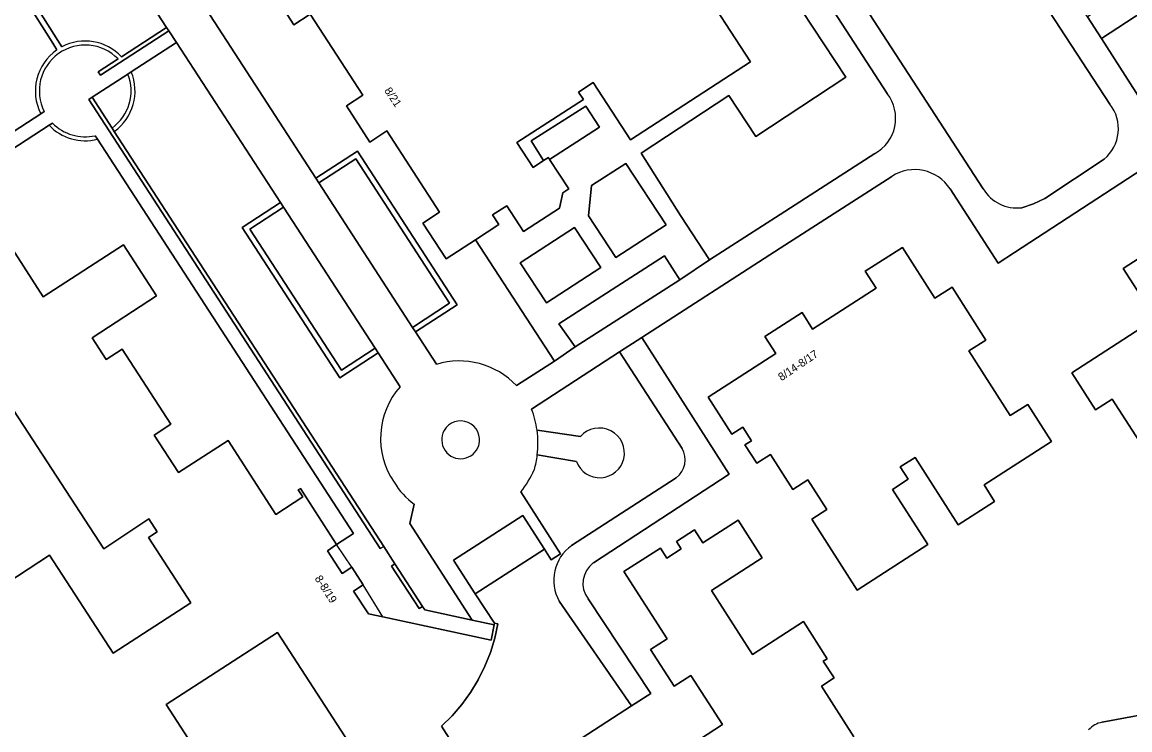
# Model space of a CAD drawing. Extents: x 159451 to 160664, y 388402 to 389723.
# Drawn here: x 159905.3 to 160043.7, y 389113.3 to 389201.7 of the extents above; entities that cross this region are included whole.
import ezdxf

# ---------------------------------------------------------------- set-up
doc = ezdxf.new("R2010")
doc.units = 0
for name, color, linetype in [('IMGEO_Erf', 7, 'Continuous'), ('IMGEO_Grasland_overig', 7, 'Continuous'), ('IMGEO_Groenvoorziening', 7, 'Continuous'), ('IMGEO_Haag', 7, 'Continuous'), ('IMGEO_Loofbos', 7, 'Continuous'), ('IMGEO_Pand', 7, 'Continuous'), ('IMGEO_Pand_nummerreeks', 7, 'Continuous'), ('IMGEO_Pand_overbouw', 7, 'Continuous'), ('IMGEO_Parkeervlak_gesloten', 7, 'Continuous'), ('IMGEO_Parkeervlak_open', 7, 'Continuous'), ('IMGEO_Rijbaan_lokaal_open', 7, 'Continuous'), ('IMGEO_Voetpad_gesloten', 7, 'Continuous'), ('IMGEO_Voetpad_open', 7, 'Continuous')]:
    doc.layers.add(name, color=color, linetype=linetype)

msp = doc.modelspace()

# ---------------------------------------------------------------- linework, layer by layer
at = {"layer": 'IMGEO_Erf'}
for points in [[(160071.89, 389220.37), (160040.16, 389199.62), (160049.04, 389185.76), (160029.31, 389172.93), (160027.27, 389171.6), (160021.26, 389180.85)], [(159908.65, 389188.8), (159892.09, 389178.04)], [(159904.05, 389173.41), (159907.94, 389167.36), (159917.95, 389173.87), (159922.1, 389167.52), (159914.03, 389162.25), (159915.78, 389159.56), (159917.79, 389160.86), (159923.89, 389151.47), (159921.79, 389150.11), (159924.82, 389145.44), (159931.02, 389149.46), (159937, 389140.22), (159940.37, 389142.4), (159939.8, 389143.29), (159940.07, 389143.45), (159944.59, 389136.47), (159946.68, 389137.83), (159914.71, 389187.05)], [(160013.96, 389182.42), (160000, 389173.44), (159982.74, 389162.32), (159993.64, 389145.22), (159976.67, 389134.17)], [(160045.85, 389166.32), (160042.88, 389170.93), (160053.34, 389177.67)], [(160046.95, 389146.17), (160041.51, 389154.6), (160039.44, 389153.27), (160036.46, 389157.9), (160049.34, 389166.2)], [(159986.93, 389110.15), (159992.8, 389113.99), (159988.87, 389120.11), (159986.77, 389118.76), (159983.82, 389123.35), (159985.9, 389124.68), (159980.5, 389133.07), (159985.06, 389136.01), (159985.86, 389134.76), (159987.65, 389135.91), (159987.08, 389136.81), (159989.33, 389138.27), (159990.37, 389136.65), (159994.76, 389139.48), (159997.77, 389134.8), (159991.42, 389130.72), (159996.56, 389122.73), (160002.93, 389126.83), (160005.91, 389122.2), (160005.41, 389121.88), (160006.76, 389119.8), (160005.18, 389118.78), (160009.24, 389112.46)], [(159976.01, 389129.66), (159983.84, 389117.87), (159981.42, 389116.3), (159963.52, 389104.72)], [(160040.24, 389114.26), (160063.58, 389118.6)]]:
    msp.add_lwpolyline(points, dxfattribs=at)
for points in [[(159999.48, 389160.31), (159998.11, 389162.44), (160002.75, 389165.41), (160004.06, 389163.36), (160012, 389168.46), (160010.64, 389170.57), (160015.3, 389173.55), (160019.36, 389167.23), (160021.49, 389168.59), (160025.73, 389161.98), (160023.6, 389160.62), (160028.77, 389152.55), (160030.95, 389153.95), (160033.92, 389149.32), (160025.49, 389143.91), (160026.82, 389141.83), (160022.27, 389138.9), (160016.87, 389147.32), (160015.03, 389146.14), (160016.02, 389144.6), (160014.05, 389143.34), (160018.47, 389136.44), (160009.63, 389130.77), (160003.97, 389139.6), (160005.86, 389140.82), (160003.48, 389144.54), (160001.6, 389143.33), (159998.8, 389147.69), (159997.1, 389146.6), (159995.62, 389148.9), (159996.44, 389149.42), (159995.36, 389151.1), (159993.98, 389150.22), (159991, 389154.87)], [(159926.37, 389129.16), (159921.08, 389137.31), (159922.18, 389138.02), (159921.11, 389139.65), (159915.48, 389135.92), (159900.68, 389158.6), (159902.96, 389160.02), (159901.31, 389162.64), (159887.76, 389154.14), (159891.55, 389148.29), (159893.57, 389149.61), (159900.41, 389139.07), (159896.4, 389136.48), (159900.67, 389129.9), (159908.73, 389135.13), (159916.68, 389122.87)], [(159951.56, 389103.31), (159937.2, 389125.47), (159923.3, 389116.46), (159937.66, 389094.3)]]:
    msp.add_lwpolyline(points, close=True, dxfattribs=at)
for centre, radius, start, end in [((159913.17, 389193.09), 6.23, 223.4934, 284.2887), ((160016.82, 389177.97), 5.29, 32.9971, 122.7747), ((159978.59, 389131.58), 3.22, 126.6873, 216.5787), ((160040.79, 389111.31), 3, 100.5123, 137.95)]:
    msp.add_arc(centre, radius, start, end, dxfattribs=at)
at = {"layer": 'IMGEO_Grasland_overig'}
for points in [[(159980.71, 389184.04), (159976.46, 389181.27), (159976.05, 389177.48), (159979.48, 389172.27), (159985.77, 389176.35)], [(159974.31, 389176.02), (159967.54, 389171.61), (159970.82, 389166.63), (159977.59, 389171.04)], [(159987.48, 389169.5), (159985.55, 389172.48), (159972.36, 389164.01), (159974.39, 389161.13)], [(159951.88, 389134.03), (159951.46, 389133.76), (159954.91, 389128.45), (159955.33, 389128.72)]]:
    msp.add_lwpolyline(points, close=True, dxfattribs=at)
at = {"layer": 'IMGEO_Groenvoorziening'}
for points in [[(159917.7, 389197.36), (159923.34, 389201.02), (159906.77, 389226.48)], [(159890.55, 389218.64), (159894.92, 389221.41), (159895.56, 389221.81), (159910.27, 389198.6)], [(159895.56, 389221.81), (159894.92, 389221.41), (159909.11, 389199.03), (159909.62, 389198.21)], [(159910.27, 389198.6), (159895.56, 389221.81)], [(159945.81, 389191.21), (159947.88, 389192.55), (159941.29, 389202.68), (159939.26, 389201.36), (159936.36, 389205.82), (159942.76, 389209.97), (159942.59, 389210.24), (159932.13, 389203.53), (159929.12, 389208.23), (159926.29, 389206.42), (159942, 389182.2), (159947.2, 389185.57), (159959.65, 389166.36), (159954.45, 389162.99), (159957.06, 389158.96)], [(160013.39, 389192.75), (160004.14, 389207.04), (160001.35, 389205.26), (160008.23, 389194.81), (159996.97, 389187.41), (159993.6, 389192.53), (159982.65, 389185.33), (159987.56, 389177.52), (159991.19, 389171.98), (160000, 389177.64), (160011.84, 389185.26)], [(159917.28, 389197.08), (159914.79, 389195.47), (159915.07, 389195.05), (159923.61, 389200.6), (159923.34, 389201.02), (159917.7, 389197.36)], [(159924.57, 389199.14), (159918.93, 389195.47)], [(159952.53, 389156.15), (159949.79, 389160.37), (159945.01, 389157.26), (159932.8, 389176.04), (159937.57, 389179.15), (159924.57, 389199.14)], [(159918.5, 389195.2), (159914.04, 389192.3), (159916.54, 389188.45)], [(159918.93, 389195.47), (159918.5, 389195.2)], [(159907.64, 389190.23), (159908.06, 389190.5)], [(159967.08, 389156.3), (159971.81, 389159.35), (159961.96, 389174.51), (159958.27, 389172.11), (159955.36, 389176.58), (159957.45, 389177.93), (159950.85, 389188.09), (159948.73, 389186.71), (159945.81, 389191.21)], [(159909.08, 389189.08), (159908.65, 389188.8)], [(159914.71, 389187.05), (159914.42, 389187.49)], [(159916.54, 389188.45), (159916.81, 389188.03)], [(159916.81, 389188.03), (159950.47, 389136.21), (159951.88, 389134.03), (159955.33, 389128.72), (159955.62, 389128.28), (159961.53, 389127.02), (159953.74, 389139.06), (159954.29, 389141.51)], [(159987.77, 389148.46), (159979.95, 389160.51), (159968.95, 389153.36)], [(159969.63, 389150.72), (159975.05, 389149.93)], [(159974.57, 389146.81), (159969.67, 389147.64)], [(159973.96, 389136.33), (159987.03, 389144.79)], [(159967.6, 389143.02), (159972.56, 389135.28), (159971.42, 389134.54), (159970.58, 389135.89), (159961.91, 389130.28), (159964.33, 389126.63), (159964.73, 389126.55), (159964.35, 389124.76), (159963.81, 389122.98), (159963.12, 389121.25), (159962.29, 389119.57), (159961.32, 389117.97), (159960.22, 389116.47), (159959.01, 389115.07), (159957.7, 389113.79), (159961.75, 389107.46), (159963.52, 389104.72), (159981.42, 389116.3), (159972.41, 389129.37)]]:
    msp.add_lwpolyline(points, dxfattribs=at)
for points in [[(159916.81, 389188.03), (159916.54, 389188.45), (159914.04, 389192.3), (159913.62, 389192.03), (159950.05, 389135.94), (159950.47, 389136.21)], [(159970.46, 389184.38), (159971.06, 389184.77), (159971.21, 389184.53), (159977.42, 389188.57), (159975.75, 389191.2), (159968.9, 389186.86)], [(159954.45, 389162.99), (159959.65, 389166.36), (159947.2, 389185.57), (159942, 389182.2), (159942.38, 389181.61), (159946.99, 389184.6), (159958.69, 389166.57), (159954.07, 389163.57)], [(159949.41, 389160.96), (159945.22, 389158.23), (159933.76, 389175.84), (159937.96, 389178.56), (159937.57, 389179.15), (159932.8, 389176.04), (159945.01, 389157.26), (159949.79, 389160.37)]]:
    msp.add_lwpolyline(points, close=True, dxfattribs=at)
for centre, radius, start, end in [((159913.17, 389193.09), 5.73, 44.2159, 206.8512), ((159913.17, 389193.09), 6.23, 43.3041, 117.7763), ((159913.17, 389193.09), 6.23, 43.3041, 117.7763), ((159913.17, 389193.09), 6.23, 124.6712, 207.3407), ((159913.17, 389193.09), 5.73, 306.0016, 21.5831), ((159913.17, 389193.09), 5.73, 306.0016, 21.5831), ((159913.17, 389193.09), 6.23, 305.7753, 22.5008), ((159913.17, 389193.09), 6.23, 305.7753, 22.5008), ((160009.42, 389189.66), 5.03, 298.8712, 37.8537), ((159913.17, 389193.09), 6.23, 223.4934, 284.2887), ((159913.17, 389193.09), 5.73, 224.4279, 282.5875), ((159959.91, 389149.48), 9.89, 43.552, 106.7454), ((159959.76, 389149.71), 9.68, 138.2961, 214.3823), ((159957.64, 389149.04), 12.11, 7.9949, 20.9234), ((159977.42, 389147.86), 3.14, 347.055, 138.8731), ((159985.31, 389147.04), 2.84, 307.436, 29.9141), ((159957.59, 389149.05), 12.16, 344.4296, 353.3315), ((159977.47, 389147.88), 3.09, 200.2256, 346.5119), ((159958.03, 389150.8), 12.33, 320.8729, 336.0275), ((159959.31, 389148.67), 8.74, 210.441, 234.976), ((159977.01, 389131.99), 5.3, 125.1, 209.6489)]:
    msp.add_arc(centre, radius, start, end, dxfattribs=at)
at = {"layer": 'IMGEO_Haag'}
for points in [[(159895.56, 389221.81), (159894.92, 389221.41), (159909.11, 389199.03), (159909.62, 389198.21)], [(159910.27, 389198.6), (159895.56, 389221.81)], [(159917.28, 389197.08), (159914.79, 389195.47), (159915.07, 389195.05), (159923.61, 389200.6), (159923.34, 389201.02), (159917.7, 389197.36)], [(159918.5, 389195.2), (159914.04, 389192.3), (159916.54, 389188.45)], [(159918.93, 389195.47), (159918.5, 389195.2)], [(159907.64, 389190.23), (159908.06, 389190.5)], [(159909.08, 389189.08), (159908.65, 389188.8)], [(159914.71, 389187.05), (159914.42, 389187.49)], [(159916.54, 389188.45), (159916.81, 389188.03)]]:
    msp.add_lwpolyline(points, dxfattribs=at)
for points in [[(159916.81, 389188.03), (159916.54, 389188.45), (159914.04, 389192.3), (159913.62, 389192.03), (159950.05, 389135.94), (159950.47, 389136.21)], [(159954.45, 389162.99), (159959.65, 389166.36), (159947.2, 389185.57), (159942, 389182.2), (159942.38, 389181.61), (159946.99, 389184.6), (159958.69, 389166.57), (159954.07, 389163.57)], [(159949.41, 389160.96), (159945.22, 389158.23), (159933.76, 389175.84), (159937.96, 389178.56), (159937.57, 389179.15), (159932.8, 389176.04), (159945.01, 389157.26), (159949.79, 389160.37)], [(159951.88, 389134.03), (159951.46, 389133.76), (159954.91, 389128.45), (159955.33, 389128.72)]]:
    msp.add_lwpolyline(points, close=True, dxfattribs=at)
for radius, start, end in [(5.73, 44.2159, 206.8512), (6.23, 43.3041, 117.7763), (6.23, 124.6712, 207.3407), (5.73, 306.0016, 21.5831), (5.73, 306.0016, 21.5831), (6.23, 305.7753, 22.5008), (6.23, 223.4934, 284.2887), (5.73, 224.4279, 282.5875)]:
    msp.add_arc((159913.17, 389193.09), radius, start, end, dxfattribs=at)
at = {"layer": 'IMGEO_Loofbos'}
msp.add_lwpolyline([(160063.58, 389118.6), (160040.24, 389114.26)], dxfattribs=at)
msp.add_arc((160040.79, 389111.31), 3, 100.5123, 137.95, dxfattribs=at)
at = {"layer": 'IMGEO_Pand'}
for points in [[(159936.36, 389205.82), (159939.26, 389201.36), (159941.29, 389202.68), (159947.88, 389192.55), (159945.81, 389191.21), (159948.73, 389186.71), (159950.85, 389188.09), (159957.45, 389177.93), (159955.36, 389176.58), (159958.27, 389172.11), (159961.96, 389174.51), (159964.86, 389176.4), (159964.08, 389177.6), (159965.87, 389178.76), (159967.96, 389175.54), (159972.46, 389178.46), (159972.87, 389180.38), (159973.6, 389180.85), (159971.21, 389184.53), (159971.06, 389184.77), (159970.46, 389184.38), (159969.15, 389183.53), (159967.13, 389186.64), (159975.43, 389192.02), (159974.82, 389192.95), (159976.66, 389194.15), (159981.31, 389186.99), (159996.29, 389196.72), (159989.51, 389207.16)], [(160053.34, 389177.67), (160042.88, 389170.93), (160045.85, 389166.32)], [(159961.75, 389107.46), (159957.7, 389113.79), (159959.01, 389115.07), (159960.22, 389116.47), (159961.32, 389117.97), (159962.29, 389119.57), (159963.12, 389121.25), (159963.81, 389122.98), (159964.35, 389124.76), (159964.73, 389126.55), (159964.33, 389126.63), (159964.29, 389126.42), (159963.89, 389124.52), (159950.37, 389127.41), (159948.58, 389127.79), (159946.7, 389130.65), (159947.9, 389131.43), (159946.48, 389133.63), (159945.27, 389132.84), (159943.44, 389135.68), (159944.59, 389136.47), (159940.07, 389143.45), (159939.8, 389143.29), (159940.37, 389142.4), (159937, 389140.22), (159931.02, 389149.46), (159924.82, 389145.44), (159921.79, 389150.11), (159923.89, 389151.47), (159917.79, 389160.86), (159915.78, 389159.56), (159914.03, 389162.25), (159922.1, 389167.52), (159917.95, 389173.87), (159907.94, 389167.36), (159904.05, 389173.41)], [(160049.34, 389166.2), (160036.46, 389157.9), (160039.44, 389153.27), (160041.51, 389154.6), (160046.95, 389146.17)], [(160009.24, 389112.46), (160005.18, 389118.78), (160006.76, 389119.8), (160005.41, 389121.88), (160005.91, 389122.2), (160002.93, 389126.83), (159996.56, 389122.73), (159991.42, 389130.72), (159997.77, 389134.8), (159994.76, 389139.48), (159990.37, 389136.65), (159989.33, 389138.27), (159987.08, 389136.81), (159987.65, 389135.91), (159985.86, 389134.76), (159985.06, 389136.01), (159980.5, 389133.07), (159985.9, 389124.68), (159983.82, 389123.35), (159986.77, 389118.76), (159988.87, 389120.11), (159992.8, 389113.99), (159986.93, 389110.15)]]:
    msp.add_lwpolyline(points, dxfattribs=at)
for points in [[(160009.63, 389130.77), (160018.47, 389136.44), (160014.05, 389143.34), (160016.02, 389144.6), (160015.03, 389146.14), (160016.87, 389147.32), (160022.27, 389138.9), (160026.82, 389141.83), (160025.49, 389143.91), (160033.92, 389149.32), (160030.95, 389153.95), (160028.77, 389152.55), (160023.6, 389160.62), (160025.73, 389161.98), (160021.49, 389168.59), (160019.36, 389167.23), (160015.3, 389173.55), (160010.64, 389170.57), (160012, 389168.46), (160004.06, 389163.36), (160002.75, 389165.41), (159998.11, 389162.44), (159999.48, 389160.31), (159991, 389154.87), (159993.98, 389150.22), (159995.36, 389151.1), (159996.44, 389149.42), (159995.62, 389148.9), (159997.1, 389146.6), (159998.8, 389147.69), (160001.6, 389143.33), (160003.48, 389144.54), (160005.86, 389140.82), (160003.97, 389139.6)], [(159916.68, 389122.87), (159908.73, 389135.13), (159900.67, 389129.9), (159896.4, 389136.48), (159900.41, 389139.07), (159893.57, 389149.61), (159891.55, 389148.29), (159887.76, 389154.14), (159901.31, 389162.64), (159902.96, 389160.02), (159900.68, 389158.6), (159915.48, 389135.92), (159921.11, 389139.65), (159922.18, 389138.02), (159921.08, 389137.31), (159926.37, 389129.16)], [(159937.66, 389094.3), (159923.3, 389116.46), (159937.2, 389125.47), (159951.56, 389103.31)]]:
    msp.add_lwpolyline(points, close=True, dxfattribs=at)
at = {"layer": 'IMGEO_Pand_overbouw'}
for points in [[(159946.48, 389133.63), (159944.59, 389136.47), (159943.44, 389135.68), (159945.27, 389132.84)], [(159950.37, 389127.41), (159947.9, 389131.43), (159946.7, 389130.65), (159948.58, 389127.79)]]:
    msp.add_lwpolyline(points, close=True, dxfattribs=at)
at = {"layer": 'IMGEO_Parkeervlak_gesloten'}
for points in [[(159891.49, 389221.76), (159884.5, 389217.18), (159885.42, 389215.73), (159881.22, 389213.01), (159898.21, 389186.19), (159902.4, 389188.91), (159903.35, 389187.45), (159907.64, 389190.23)], [(159909.62, 389198.21), (159909.11, 389199.03), (159894.92, 389221.41)]]:
    msp.add_lwpolyline(points, dxfattribs=at)
for points in [[(159954.07, 389163.57), (159958.69, 389166.57), (159946.99, 389184.6), (159942.38, 389181.61)], [(159937.96, 389178.56), (159933.76, 389175.84), (159945.22, 389158.23), (159949.41, 389160.96)]]:
    msp.add_lwpolyline(points, close=True, dxfattribs=at)
msp.add_arc((159913.17, 389193.09), 6.23, 124.6712, 207.3407, dxfattribs=at)
at = {"layer": 'IMGEO_Parkeervlak_open'}
msp.add_lwpolyline([(159967.86, 389140.08), (159959.2, 389134.48), (159961.91, 389130.28), (159970.58, 389135.89)], close=True, dxfattribs=at)
at = {"layer": 'IMGEO_Rijbaan_lokaal_open'}
for points in [[(159906.77, 389226.48), (159923.34, 389201.02), (159923.61, 389200.6), (159924.57, 389199.14), (159937.57, 389179.15), (159937.96, 389178.56), (159949.41, 389160.96), (159949.79, 389160.37), (159952.53, 389156.15)], [(160027.09, 389219.58), (160023.88, 389224.68), (160006.59, 389213.4), (160005.34, 389212.58), (160001.98, 389210.39), (160002.85, 389209.04), (160004.14, 389207.04), (160013.39, 389192.75)], [(160025.35, 389215.76), (160041.22, 389191.43)], [(159957.06, 389158.96), (159954.45, 389162.99), (159954.07, 389163.57), (159942.38, 389181.61), (159942, 389182.2), (159926.29, 389206.42), (159924.29, 389209.5), (159922.23, 389212.7)], [(160021.26, 389180.85), (160027.27, 389171.6), (160029.31, 389172.93), (160049.04, 389185.76), (160040.16, 389199.62), (160038.43, 389202.32), (160034.78, 389207.9)], [(160025.38, 389180.86), (160009.52, 389205.29)], [(160011.84, 389185.26), (160000, 389177.64), (159991.19, 389171.98), (159987.48, 389169.5), (159974.39, 389161.13), (159971.81, 389159.35), (159967.08, 389156.3)], [(160040.51, 389184.57), (160033.09, 389179.66), (160031.69, 389178.97), (160030.2, 389178.51)], [(159968.95, 389153.36), (159979.95, 389160.51), (159982.74, 389162.32), (160000, 389173.44), (160013.96, 389182.42)], [(159954.29, 389141.51), (159953.74, 389139.06), (159961.53, 389127.02), (159964.29, 389126.42), (159964.33, 389126.63), (159961.91, 389130.28), (159959.2, 389134.48), (159967.86, 389140.08), (159970.58, 389135.89), (159971.42, 389134.54), (159972.56, 389135.28), (159967.6, 389143.02)]]:
    msp.add_lwpolyline(points, dxfattribs=at)
for centre, radius, start, end in [((160009.42, 389189.66), 5.03, 298.8712, 37.8537), ((160037.32, 389188.37), 4.96, 309.9008, 38.181), ((160016.82, 389177.97), 5.29, 32.9971, 122.7747), ((160029.64, 389183.48), 5.01, 211.6208, 276.396), ((159959.91, 389149.48), 9.89, 43.552, 106.7454), ((159959.76, 389149.71), 9.68, 138.2961, 214.3823), ((159957.64, 389149.04), 12.11, 7.9949, 20.9234), ((159960.08, 389149.52), 2.37, 343.1217, 150.2575), ((159960.08, 389149.52), 2.37, 343.1217, 150.2575), ((159960.09, 389149.53), 2.37, 150.4782, 342.9011), ((159960.09, 389149.53), 2.37, 150.4782, 342.9011), ((159957.64, 389149.04), 12.11, 353.3656, 7.9741), ((159957.59, 389149.05), 12.16, 344.4296, 353.3315), ((159958.03, 389150.8), 12.33, 320.8729, 336.0275), ((159959.31, 389148.67), 8.74, 210.441, 234.976)]:
    msp.add_arc(centre, radius, start, end, dxfattribs=at)
at = {"layer": 'IMGEO_Voetpad_gesloten'}
for points in [[(160069.88, 389222.95), (160059.58, 389216.09), (160038.43, 389202.32), (160040.16, 389199.62), (160071.89, 389220.37)], [(160041.22, 389191.43), (160025.35, 389215.76)], [(160009.52, 389205.29), (160025.38, 389180.86)], [(160030.2, 389178.51), (160031.69, 389178.97), (160033.09, 389179.66), (160040.51, 389184.57)], [(159993.64, 389145.22), (159982.74, 389162.32), (159979.95, 389160.51), (159987.77, 389148.46)], [(159987.03, 389144.79), (159973.96, 389136.33)], [(159976.67, 389134.17), (159993.64, 389145.22)], [(159972.41, 389129.37), (159981.42, 389116.3), (159983.84, 389117.87), (159976.01, 389129.66)]]:
    msp.add_lwpolyline(points, dxfattribs=at)
for centre, radius, start, end in [((160037.32, 389188.37), 4.96, 309.9008, 38.181), ((160029.64, 389183.48), 5.01, 211.6208, 276.396), ((159985.31, 389147.04), 2.84, 307.436, 29.9141), ((159977.01, 389131.99), 5.3, 125.1, 209.6489), ((159978.59, 389131.58), 3.22, 126.6873, 216.5787)]:
    msp.add_arc(centre, radius, start, end, dxfattribs=at)
at = {"layer": 'IMGEO_Voetpad_open'}
for points in [[(159989.51, 389207.16), (159996.29, 389196.72), (159981.31, 389186.99), (159976.66, 389194.15), (159974.82, 389192.95), (159975.43, 389192.02), (159967.13, 389186.64), (159969.15, 389183.53), (159970.46, 389184.38), (159968.9, 389186.86), (159975.75, 389191.2), (159977.42, 389188.57), (159971.21, 389184.53), (159973.6, 389180.85), (159972.87, 389180.38), (159972.46, 389178.46), (159967.96, 389175.54), (159965.87, 389178.76), (159964.08, 389177.6), (159964.86, 389176.4), (159961.96, 389174.51), (159971.81, 389159.35), (159974.39, 389161.13), (159972.36, 389164.01), (159985.55, 389172.48), (159987.48, 389169.5), (159991.19, 389171.98), (159987.56, 389177.52), (159982.65, 389185.33), (159993.6, 389192.53), (159996.97, 389187.41), (160008.23, 389194.81), (160001.35, 389205.26)], [(159918.5, 389195.2), (159918.93, 389195.47), (159924.57, 389199.14), (159923.61, 389200.6), (159915.07, 389195.05), (159914.79, 389195.47), (159917.28, 389197.08)], [(159914.42, 389187.49), (159914.71, 389187.05), (159946.68, 389137.83), (159944.59, 389136.47), (159943.44, 389135.68), (159945.27, 389132.84), (159946.48, 389133.63), (159947.9, 389131.43), (159946.7, 389130.65), (159948.58, 389127.79), (159950.37, 389127.41), (159963.89, 389124.52), (159964.29, 389126.42), (159961.53, 389127.02), (159955.62, 389128.28), (159955.33, 389128.72), (159954.91, 389128.45), (159951.46, 389133.76), (159951.88, 389134.03), (159950.47, 389136.21), (159950.05, 389135.94), (159913.62, 389192.03), (159914.04, 389192.3), (159918.5, 389195.2)], [(159908.06, 389190.5), (159907.64, 389190.23), (159903.35, 389187.45), (159891.13, 389179.51), (159892.09, 389178.04), (159908.65, 389188.8), (159909.08, 389189.08)], [(159975.05, 389149.93), (159969.63, 389150.72)], [(159969.67, 389147.64), (159974.57, 389146.81)]]:
    msp.add_lwpolyline(points, dxfattribs=at)
for points in [[(159976.46, 389181.27), (159980.71, 389184.04), (159985.77, 389176.35), (159979.48, 389172.27), (159976.05, 389177.48)], [(159967.54, 389171.61), (159974.31, 389176.02), (159977.59, 389171.04), (159970.82, 389166.63)]]:
    msp.add_lwpolyline(points, close=True, dxfattribs=at)
for centre, radius, start, end in [((159913.17, 389193.09), 5.73, 44.2159, 206.8512), ((159913.17, 389193.09), 5.73, 224.4279, 282.5875), ((159957.64, 389149.04), 12.11, 353.3656, 7.9741), ((159977.42, 389147.86), 3.14, 347.055, 138.8731), ((159977.47, 389147.88), 3.09, 200.2256, 346.5119)]:
    msp.add_arc(centre, radius, start, end, dxfattribs=at)

# ---------------------------------------------------------------- texts
at = {"layer": 'IMGEO_Pand_nummerreeks'}
for s, rotation, p in [('8/21', 303.747, (159950.5, 389193.13)), ('8/14-8/17', 33.9538, (160000.18, 389156.83)), ('8-8/19', 302.812, (159941.81, 389132.21))]:
    msp.add_text(s, height=1, rotation=rotation, dxfattribs=at).set_placement(p)

doc.saveas('drawing.dxf')
